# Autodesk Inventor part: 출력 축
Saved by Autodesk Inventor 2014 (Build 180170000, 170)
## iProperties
Created: 2026-04
Part Number: 출력 축
Material: 강철, 탄소
Document SubType Name: Modeling
Designer: dg
Density: 7.87 g/cm^3
Appearance: 반연마
Author: jhkim
Creation Date: 2026-03-27
Sending System: Autodesk Inventor 2026
Preprocessor: ST-DEVELOPER v20.1
Author: dg
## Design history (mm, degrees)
node "출력 축1"
node "솔리드1"
node "기준1"
